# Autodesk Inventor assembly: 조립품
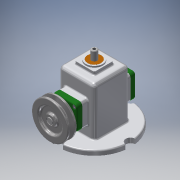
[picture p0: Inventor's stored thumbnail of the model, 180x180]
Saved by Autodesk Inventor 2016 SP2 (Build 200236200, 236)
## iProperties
Created: 2018-07
Part Number: 조립품
Document SubType Name: Assembly
Designer: Administrator
Author: Administrator
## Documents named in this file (16)
- Z:\인벤터기술자격증시험\480707V1004 김영호\480707V1004\조립품.iam
- Z:\인벤터기술자격증시험\480707V1004 김영호\480707V1004\본체.ipt
- Z:\인벤터기술자격증시험\480707V1004 김영호\480707V1004\앞커버.ipt
- Z:\인벤터기술자격증시험\480707V1004 김영호\480707V1004\뒤커버.ipt
- Z:\인벤터기술자격증시험\480707V1004 김영호\480707V1004\편심축.ipt
- Z:\인벤터기술자격증시험\480707V1004 김영호\480707V1004\베어링 12x32x10.ipt
- Z:\인벤터기술자격증시험\480707V1004 김영호\480707V1004\볼트 M4.ipt
- Z:\인벤터기술자격증시험\480707V1004 김영호\480707V1004\키 4x4x10.ipt
- Z:\인벤터기술자격증시험\480707V1004 김영호\480707V1004\V벨트풀리.ipt
- Z:\인벤터기술자격증시험\480707V1004 김영호\480707V1004\멈춤나사 M3x8.ipt
- Z:\인벤터기술자격증시험\480707V1004 김영호\480707V1004\링크.ipt
- Z:\인벤터기술자격증시험\480707V1004 김영호\480707V1004\슬라이드.ipt
- Z:\인벤터기술자격증시험\480707V1004 김영호\480707V1004\핀 5x18.ipt
- Z:\인벤터기술자격증시험\480707V1004 김영호\480707V1004\고정핀 1.2x8.ipt
- Z:\인벤터기술자격증시험\480707V1004 김영호\480707V1004\부시.ipt
- Z:\인벤터기술자격증시험\480707V1004 김영호\480707V1004\오일 실 12 25 7.ipt
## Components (3 placed, 3 different names)
1. V벨트풀리:1
2. 핀 5x18:1
3. 고정핀 1.2x8:1
